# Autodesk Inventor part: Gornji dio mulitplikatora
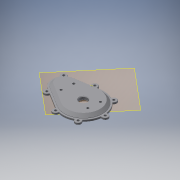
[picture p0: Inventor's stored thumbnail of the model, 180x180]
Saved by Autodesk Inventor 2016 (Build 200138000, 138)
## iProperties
Created: 2015-08
Part Number: Gornji dio mulitplikatora
Material: Generic
Document SubType Name: Modeling
Designer: stank
Density: 1 g/cm^3
Appearance: Default
Author: stank
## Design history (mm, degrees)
workplane "Work Plane1"
sketch "Sketch1"
  geometry: L1 (-33.028, 42.698)-(27.802, -9.971) reference; L2 (-79.077, -68.402)-(-90.579, 11.235) reference; L3 (-95.528, 10.521)-(-95.242, 8.541) reference; L4 (-100.047, 6.837)-(-96.088, 7.409) reference; L5 (-93.23, -12.386)-(-97.189, -12.958) reference; L6 (-92.097, -13.233)-(-84.026, -69.117) reference; L7 (-84.078, -73.704)-(-87.967, -75.12) reference; L8 (-81.127, -93.914)-(-77.237, -92.498) reference; L9 (-42.558, -124.275)-(-43.63, -128.273) reference; L10 (-24.311, -133.45)-(-23.24, -129.452) reference; L11 (22.682, -119.271)-(25.342, -122.442) reference; L12 (40.663, -109.586)-(38.003, -106.415) reference; L13 (56.003, -62.959)-(60.126, -62.599) reference; L14 (58.383, -42.675)-(54.26, -43.035) reference; L15 (31.075, -6.191)-(23.921, 0.004) reference; L16 (23.819, 1.415)-(26.437, 4.439) reference; L17 (11.317, 17.53)-(8.699, 14.506) reference; L18 (7.289, 14.405)-(-29.755, 46.478) reference; L19 (-42.165, 58.93)-(-42.534, 54.713) reference; L20 (-62.458, 56.457)-(-62.089, 60.673) reference; C1 r 4 at (-52.127, 59.802) reference; C2 r 4 at (18.877, 10.984) reference; C3 r 4 at (-98.618, -3.06) reference; C4 r 4 at (-84.547, -84.517) reference; C5 r 4 at (-33.97, -130.862) reference; C6 r 4 at (33.003, -116.014) reference; C7 r 4 at (59.255, -52.637) reference; A1 r 35 centre (-55.938, 16.238) between (-33.028, 42.698) and (-90.579, 11.235) reference; A2 r 65 centre (-14.745, -59.111) between (-79.077, -68.402) and (27.802, -9.971) reference; A3 r 40 centre (-55.938, 16.238) between (-63.271, 55.561) and (-95.528, 10.521) reference; A4 r 1 centre (-96.231, 8.398) between (-96.088, 7.409) and (-95.242, 8.541) reference; A5 r 10 centre (-98.618, -3.06) between (-100.047, 6.837) and (-97.189, -12.958) reference; A6 r 1 centre (-93.087, -13.376) between (-92.097, -13.233) and (-93.23, -12.386) reference; A7 r 70 centre (-14.745, -59.111) between (-84.026, -69.117) and (-83.438, -72.572) reference; A8 r 1 centre (-84.42, -72.764) between (-84.078, -73.704) and (-83.438, -72.572) reference; A9 r 10 centre (-84.547, -84.517) between (-87.967, -75.12) and (-81.127, -93.914) reference; A10 r 1 centre (-76.895, -93.437) between (-76.02, -92.954) and (-77.237, -92.498) reference; A11 r 70 centre (-14.745, -59.111) between (-76.02, -92.954) and (-43.119, -123.102) reference; A12 r 1 centre (-43.524, -124.016) between (-42.558, -124.275) and (-43.119, -123.102) reference; A13 r 10 centre (-33.97, -130.862) between (-43.63, -128.273) and (-24.311, -133.45) reference; A14 r 1 centre (-22.274, -129.71) between (-22.168, -128.716) and (-23.24, -129.452) reference; A15 r 70 centre (-14.745, -59.111) between (-22.168, -128.716) and (21.399, -119.057) reference; A16 r 1 centre (21.916, -119.914) between (22.682, -119.271) and (21.399, -119.057) reference; A17 r 10 centre (33.003, -116.014) between (25.342, -122.442) and (40.663, -109.586) reference; A18 r 1 centre (38.769, -105.772) between (38.015, -105.115) and (38.003, -106.415) reference; A19 r 70 centre (-14.745, -59.111) between (38.015, -105.115) and (55.092, -63.887) reference; A20 r 1 centre (56.09, -63.955) between (56.003, -62.959) and (55.092, -63.887) reference; A21 r 10 centre (59.255, -52.637) between (60.126, -62.599) and (58.383, -42.675) reference; A22 r 1 centre (54.172, -42.039) between (53.202, -42.28) and (54.26, -43.035) reference; A23 r 70 centre (-14.745, -59.111) between (53.202, -42.28) and (31.075, -6.191) reference; A24 r 1 centre (24.575, 0.76) between (23.819, 1.415) and (23.921, 0.004) reference; A25 r 10 centre (18.877, 10.984) between (26.437, 4.439) and (11.317, 17.53) reference; A26 r 1 centre (7.943, 15.161) between (7.289, 14.405) and (8.699, 14.506) reference; A27 r 40 centre (-55.938, 16.238) between (-29.755, 46.478) and (-41.889, 53.69) reference; A28 r 1 centre (-41.538, 54.626) between (-42.534, 54.713) and (-41.889, 53.69) reference; A29 r 10 centre (-52.127, 59.802) between (-42.165, 58.93) and (-62.089, 60.673) reference; A30 r 1 centre (-63.454, 56.544) between (-63.271, 55.561) and (-62.458, 56.457) reference; 1 further point
extrude "Extrusion1" new body sketch "Sketch1" distance "d0" = 6; taper "d1" = 0 deg
sketch "Sketch2"
  geometry: L1 (-42.698, -33.028)-(9.971, 27.802) reference; L2 (68.402, -79.077)-(-11.235, -90.579) reference; C1 r 13.5 at (59.111, -14.745); C2 r 10 at (59.111, -14.745) reference; A1 r 65 centre (59.111, -14.745) between (68.402, -79.077) and (9.971, 27.802) reference; A2 r 35 centre (-16.238, -55.938) between (-42.698, -33.028) and (-11.235, -90.579) reference; 1 further point
  constraints: 1 centre point, 1 coincident
  dimensions: "d24" = 27 diameter of C1
  node "Reference9"
workplane "Work Plane3"
sketch "Sketch4"
  geometry: C1 r 23.5 at (11.642, -52.082) reference; C2 r 12.5 at (11.642, -52.082) reference; C3 r 13.5 at (11.642, -52.082); C4 r 13.1 at (-59.111, -14.745) reference; C5 r 14.1 at (-59.111, -14.745)
  constraints: 2 centre point, 2 coincident
  dimensions: "d10" = 1 radial gap between concentric circles of C2 C3; "d27" = 1 radial gap between concentric circles of C5 C4
extrude "Extrusion5" join sketch "Sketch4" distance "d11" = 1; taper "d12" = 0 deg
workplane "Work Plane2"
sketch "Sketch5"
  geometry: C1 r 23.5 at (11.642, -52.082) reference; C2 r 23.5 at (-57.817, -12.389) reference; C3 r 26.5 at (11.642, -52.082); C4 r 26.5 at (-57.817, -12.389); 1 further point
  constraints: 2 centre point, 2 coincident
  dimensions: "d14" = 3 radial gap between concentric circles of C2 C4; "d15" = 3 radial gap between concentric circles of C3 C1
extrude "Extrusion6" join sketch "Sketch5" distance "d16" = 13; taper "d17" = 0 deg
fillet "Fillet3" dims "d22" = 1
extrude "Extrusion7" join sketch "Sketch2" distance "d25" = 10; taper "d26" = 0 deg
chamfer "Chamfer2" distance "d29" = 9; stored, may be unused: second distance "d30" = 2, angle "d31" = 45 deg
chamfer "Chamfer3" distance "d32" = 2; stored, may be unused: second distance "d33" = 2, angle "d34" = 45 deg
sketch "Sketch6" dims "d49" = 80
  geometry: L1 (-16.238, -55.938)-(-16.238, 41.168); L2 (-16.238, -55.938)-(36.668, -55.938); L3 (59.111, 45.037)-(59.111, -79.06); L4 (13.728, -14.745)-(111.292, -14.745); L5 (-16.238, -55.938)-(2.146, -37.553); L6 (59.111, -14.745)-(87.395, 13.54); L7 (59.111, -14.745)-(87.395, -43.029); L8 (59.111, -14.745)-(30.826, 13.54); L9 (59.111, -14.745)-(30.826, -43.029); A1 r 56 centre (59.111, -14.745) between (67.115, -70.17) and (16.775, 21.911) reference; A2 r 26 centre (-16.238, -55.938) between (-35.894, -38.919) and (-12.522, -81.671) reference; A3 r 26 centre (-16.238, -55.938) between (-16.238, -29.938) and (2.146, -37.553); 9 further points
  constraints: 18 end point, 9 point on line, 5 coincident, 4 point on circle, 2 horizontal, 2 vertical, 1 centre point, 1 concentric, 11 other
  dimensions: "d50" = 45 deg angle of L2 L5; "d51" = 45 deg angle of L4 L6; "d52" = 45 deg angle of L4 L8; "d53" = 45 deg angle of L4 L9; "d54" = 45 deg angle of L4 L7
hole "Hole1" sketch "Sketch6" at (-16.238, -29.938), (2.146, -37.553), (9.762, -55.938), (59.111, -54.745), (88.579, -41.793), (99.111, -14.745), (87.395, 13.54), (59.111, 25.255), (30.826, 13.54), (19.111, -14.745), (30.826, -43.029) diameter "d39" = 8; stored, may be unused: countersink angle "d43" = 90 deg, drill point angle "d45" = 118 deg; dims "d40" = 6, "d41" = 4, "d42" = 2, "d44" = 6
body "Solid1"
node "Reference1"
node "Reference11"
